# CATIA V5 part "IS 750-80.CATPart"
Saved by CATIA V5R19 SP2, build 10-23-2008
Part number: IS 750-80
Bounding box of the stored display mesh (mm): x -24.865 to 24.865, y -24.997 to 24.997, z 0 to 255
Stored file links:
  C:\Users\Bora\Desktop\3D Katı model\IS serisi\IS 750\IS 750-80.CATPart
  C:\Program Files\Dassault Systemes\B19\intel_a\reffiles\standard\MetricThickPitch.txt
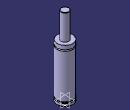
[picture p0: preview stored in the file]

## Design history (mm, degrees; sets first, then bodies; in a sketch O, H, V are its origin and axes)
Body1 (main body)
  Sketch1 on yz-plane, origin (0, 0, 0), H (0, 1, 0), V (0, 0, 1)
    point P1 (25, 159.5)
    point P4 (25, 155.5)
    point P7 (12.5, 254)
    point P9 (12.5, 254)
    point P13 (25, 159.5)
    point P14 (25, 155.5)
    line L1 (25, 159.5) -> (25, 172)
    line L2 (25, 13) -> (25, 155.5)
    line L3 (21.5, 13) -> (21.5, 8)
    arc A1 centre (11.5, 254) radius 1 from (12.5, 254) to (11.5, 255) ccw
    line L4 (12.5, 254) -> (12.5, 172)
    line L5 (25, 0) -> (25, 8)
    arc A2 centre (25, 157.5) radius 2 from (25, 159.5) to (25, 155.5) ccw
    line L6 (11.5, 255) -> (0, 255)
    point P15 (0, 255)
    line L7 (12.5, 172) -> (25, 172)
    line L8 (0, 0) -> (25, 0)
    line L9 (21.5, 8) -> (25, 8)
    line L10 (21.5, 13) -> (25, 13)
    coincidence: P15 V, P1 P13, P4 P14, P7 P9
    tangency: L6 A1
    horizontal: L7 H, L8 H, L9 H, L10 H
  Shaft1: profile Sketch1, axis Sketch1.V, angle 360
  Sketch2 on face of Shaft1 from Sketch1.L8, origin (0, 0, 0), H (1, 0, 0), V (0, -1, 0)
    point P1 (10, 0)
    distance P1 V = 10
  Hole1: placed by Sketch2, at (10, 0, 0) direction (0, 0, 1), diameter 6.647, depth 13, threaded "M8", thread diameter 8, thread depth 13, pitch 1.25
  Sketch3 on face of Shaft1 from Sketch1.L8, origin (0, 0, 0), H (1, 0, 0), V (0, -1, 0)
    point P1 (-10, 0)
    distance P1 V = 10
  Hole2: placed by Sketch3, at (-10, 0, 0) direction (0, 0, 1), diameter 6.647, depth 13, threaded "M8", thread diameter 8, thread depth 13, pitch 1.25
